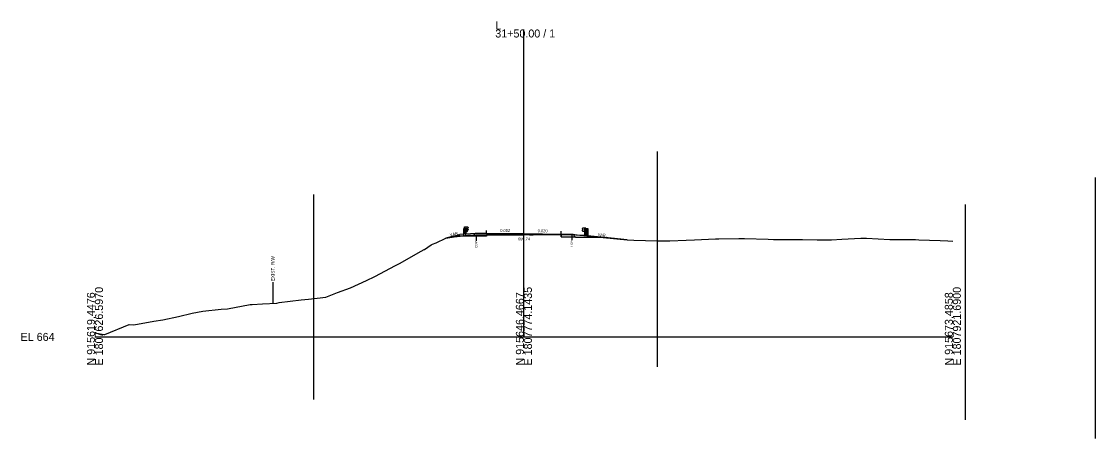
# Model space of a CAD drawing. Extents: x -26 to 1352, y -510 to 9596.
# Drawn here: x 974.3 to 1349.9, y 7464.5 to 7610.3 of the extents above; entities that cross this region are included whole.
import ezdxf

# ---------------------------------------------------------------- set-up
doc = ezdxf.new("R2010")
doc.units = 0
for name, color, linetype in [('Exist Cross Section Cell', 7, 'Continuous'), ('Exist XS Center Line Elevation Label', 7, 'Continuous'), ('Exist XS Ground Line', 7, 'Continuous'), ('Old_Level_10', 7, 'Continuous'), ('Prop XS Ditch Slope Text', 7, 'Continuous'), ('Prop XS Earthwork Shape', 7, 'Continuous'), ('Prop XS EOT Tick Mark', 7, 'Continuous'), ('Prop XS Exc Vertical Line 1', 7, 'Continuous'), ('Prop XS Exc Vertical Line 2', 7, 'Continuous'), ('Prop XS Exc Vertical Line 3', 7, 'Continuous'), ('Prop XS Exc Vertical Line 4', 7, 'Continuous'), ('Prop XS Finish Grade', 7, 'Continuous'), ('Prop XS Finish Grade Earthwork', 7, 'Continuous'), ('Prop XS Finish Grade Paved Shoulder', 7, 'Continuous'), ('Prop XS Finish Grade Pavement', 7, 'Continuous'), ('Prop XS Guardrail', 7, 'Continuous'), ('Prop XS Pvmt Edge Slope', 7, 'Continuous'), ('Prop XS SE Text', 7, 'Continuous'), ('Prop XS Subgrade Earthwork', 7, 'Continuous'), ('Scratch_Level_6', 7, 'Continuous')]:
    doc.layers.add(name, color=color, linetype=linetype)

msp = doc.modelspace()

# ---------------------------------------------------------------- linework, layer by layer
at = {"layer": 'Exist Cross Section Cell'}
for p, q in [((1150, 7500), (1150, 7607.46)), ((1000, 7500), (1150, 7500)), ((1150, 7500), (1300, 7500))]:
    msp.add_line(p, q, dxfattribs=at)
at = {"layer": 'Exist XS Ground Line'}
msp.add_lwpolyline([(1000, 7501.46), (1003.07, 7500.9), (1003.4, 7500.86), (1003.46, 7500.86), (1011.99, 7504.38), (1013.63, 7504.24), (1020.58, 7505.51), (1023.79, 7505.98), (1029.18, 7507.19), (1033.96, 7508.32), (1037.77, 7509.01), (1044.12, 7509.68), (1046.36, 7509.82), (1054.29, 7511.33), (1054.96, 7511.36), (1058.58, 7511.59), (1063.55, 7511.83), (1064.46, 7511.97), (1072.14, 7512.93), (1074.62, 7513.25), (1080.73, 7513.88), (1084.79, 7515.53), (1089.33, 7517.18), (1094.96, 7519.77), (1097.92, 7521.17), (1105.12, 7524.92), (1106.51, 7525.64), (1114.1, 7529.93), (1115.1, 7530.5), (1115.29, 7530.6), (1117.61, 7532.13), (1118.09, 7532.44), (1119.28, 7532.94), (1122.72, 7534.5), (1125.6, 7534.97), (1130.31, 7535.57), (1132.65, 7535.63), (1133.11, 7535.62), (1133.26, 7535.63), (1134.49, 7535.63), (1134.87, 7535.63), (1134.93, 7535.64), (1137, 7535.64), (1137.38, 7535.65), (1137.67, 7535.65), (1139.92, 7535.69), (1140.8, 7535.68), (1142.46, 7535.68), (1143.61, 7535.67), (1145, 7535.68), (1146.65, 7535.71), (1147.71, 7535.72), (1147.9, 7535.72), (1148.95, 7535.72), (1149.15, 7535.72), (1149.26, 7535.72), (1149.89, 7535.73), (1150, 7535.74), (1150.09, 7535.74), (1150.36, 7535.74), (1151.93, 7535.72), (1152.63, 7535.71), (1153.22, 7535.72), (1155.17, 7535.76), (1156.33, 7535.75), (1157.7, 7535.75), (1159.45, 7535.77), (1160.24, 7535.78), (1161.83, 7535.8), (1161.86, 7535.8), (1161.91, 7535.8), (1162.79, 7535.79), (1163.8, 7535.79), (1165.33, 7535.79), (1165.5, 7535.8), (1166.71, 7535.82), (1170.98, 7535.42), (1172, 7535.32), (1172.3, 7535.3), (1172.44, 7535.28), (1173.08, 7535.22), (1174.13, 7535.13), (1186.13, 7533.94), (1188.4, 7533.86), (1196.62, 7533.53), (1201.03, 7533.6), (1206.79, 7533.85), (1209.62, 7533.97), (1216.95, 7534.31), (1218.22, 7534.34), (1225.13, 7534.39), (1226.81, 7534.4), (1227.12, 7534.4), (1235.4, 7534.14), (1237.28, 7534.1), (1244, 7534.05), (1247.45, 7534.01), (1252.59, 7533.92), (1257.62, 7533.98), (1261.18, 7534.14), (1267.78, 7534.56), (1269.77, 7534.54), (1277.95, 7534.04), (1278.37, 7534.02), (1280.65, 7534.01), (1286.96, 7534.03), (1288.12, 7533.91), (1295.55, 7533.66), (1298.28, 7533.59), (1300, 7533.49)], dxfattribs=at)
at = {"layer": 'Old_Level_10'}
for p, q in [((1133.26, 7535.63), (1133.26, 7533.58)), ((1166.71, 7535.82), (1166.71, 7533.77)), ((1062.2, 7519.17), (1062.2, 7511.77))]:
    msp.add_line(p, q, dxfattribs=at)
at = {"layer": 'Prop XS Earthwork Shape'}
for points in [[(1125.6, 7534.97), (1127.74, 7535.25), (1125.39, 7535.24), (1122.72, 7534.5)], [(1122.72, 7534.5), (1125.39, 7535.24), (1127.74, 7535.25), (1125.6, 7534.97)], [(1122.72, 7534.5), (1125.39, 7535.24), (1127.74, 7535.25), (1125.6, 7534.97)], [(1122.72, 7534.5), (1125.39, 7535.24), (1127.74, 7535.25), (1125.6, 7534.97)], [(1125.6, 7534.97), (1127.74, 7535.25), (1125.39, 7535.24), (1122.72, 7534.5)], [(1134.49, 7535.63), (1134.87, 7535.63), (1134.93, 7535.64), (1136.91, 7535.64), (1136.91, 7535.26), (1131.99, 7535.25), (1127.74, 7535.25), (1130.31, 7535.57), (1132.65, 7535.63), (1133.11, 7535.62), (1133.26, 7535.63)], [(1127.74, 7535.25), (1130.31, 7535.57), (1132.65, 7535.63), (1133.11, 7535.62), (1133.26, 7535.63), (1134.49, 7535.63), (1134.87, 7535.63), (1134.93, 7535.64), (1136.91, 7535.64), (1136.91, 7535.26), (1131.99, 7535.25)], [(1133.11, 7535.62), (1133.26, 7535.63), (1134.49, 7535.63), (1134.87, 7535.63), (1134.93, 7535.64), (1136.91, 7535.64), (1136.91, 7535.26), (1131.99, 7535.25), (1127.74, 7535.25), (1130.31, 7535.57), (1132.65, 7535.63)], [(1133.11, 7535.62), (1133.26, 7535.63), (1134.49, 7535.63), (1134.87, 7535.63), (1134.93, 7535.64), (1136.91, 7535.64), (1136.91, 7535.26), (1131.99, 7535.25), (1127.74, 7535.25), (1130.31, 7535.57), (1132.65, 7535.63)], [(1134.49, 7535.63), (1134.87, 7535.63), (1134.93, 7535.64), (1136.91, 7535.64), (1136.91, 7535.26), (1131.99, 7535.25), (1127.74, 7535.25), (1130.31, 7535.57), (1132.65, 7535.63), (1133.11, 7535.62), (1133.26, 7535.63)], [(1173.08, 7535.22), (1174.13, 7535.13), (1178.3, 7534.72), (1168.03, 7534.92), (1163.09, 7535.02), (1163.09, 7535.79), (1163.8, 7535.79), (1165.33, 7535.79), (1165.5, 7535.8), (1166.71, 7535.82), (1170.98, 7535.42), (1172, 7535.32), (1172.3, 7535.3), (1172.44, 7535.28)], [(1174.13, 7535.13), (1178.3, 7534.72), (1168.03, 7534.92), (1163.09, 7535.02), (1163.09, 7535.79), (1163.8, 7535.79), (1165.33, 7535.79), (1165.5, 7535.8), (1166.71, 7535.82), (1170.98, 7535.42), (1172, 7535.32), (1172.3, 7535.3), (1172.44, 7535.28), (1173.08, 7535.22)], [(1163.09, 7535.79), (1163.8, 7535.79), (1165.33, 7535.79), (1165.5, 7535.8), (1166.71, 7535.82), (1170.98, 7535.42), (1172, 7535.32), (1172.3, 7535.3), (1172.44, 7535.28), (1173.08, 7535.22), (1174.13, 7535.13), (1178.3, 7534.72), (1168.03, 7534.92), (1163.09, 7535.02)], [(1163.09, 7535.79), (1163.8, 7535.79), (1165.33, 7535.79), (1165.5, 7535.8), (1166.71, 7535.82), (1170.98, 7535.42), (1172, 7535.32), (1172.3, 7535.3), (1172.44, 7535.28), (1173.08, 7535.22), (1174.13, 7535.13), (1178.3, 7534.72), (1168.03, 7534.92), (1163.09, 7535.02)], [(1173.08, 7535.22), (1174.13, 7535.13), (1178.3, 7534.72), (1168.03, 7534.92), (1163.09, 7535.02), (1163.09, 7535.79), (1163.8, 7535.79), (1165.33, 7535.79), (1165.5, 7535.8), (1166.71, 7535.82), (1170.98, 7535.42), (1172, 7535.32), (1172.3, 7535.3), (1172.44, 7535.28)], [(1179.32, 7534.7), (1186.13, 7533.94), (1178.3, 7534.72)], [(1179.32, 7534.7), (1186.13, 7533.94), (1178.3, 7534.72)], [(1179.32, 7534.7), (1186.13, 7533.94), (1178.3, 7534.72)], [(1179.32, 7534.7), (1186.13, 7533.94), (1178.3, 7534.72)]]:
    msp.add_lwpolyline(points, close=True, dxfattribs=at)
at = {"layer": 'Prop XS EOT Tick Mark'}
for p, q in [((1136.91, 7536.18), (1136.91, 7537.18)), ((1163.09, 7535.94), (1163.09, 7536.94))]:
    msp.add_line(p, q, dxfattribs=at)
at = {"layer": 'Prop XS Exc Vertical Line 1'}
msp.add_line((1076.49, 7478.17), (1076.49, 7549.82), dxfattribs=at)
at = {"layer": 'Prop XS Exc Vertical Line 2'}
msp.add_line((1196.7, 7489.53), (1196.7, 7564.76), dxfattribs=at)
at = {"layer": 'Prop XS Exc Vertical Line 3'}
msp.add_line((1304.41, 7471), (1304.41, 7546.24), dxfattribs=at)
at = {"layer": 'Prop XS Exc Vertical Line 4'}
msp.add_line((1349.89, 7464.49), (1349.89, 7555.68), dxfattribs=at)
at = {"layer": 'Prop XS Finish Grade'}
for p, q in [((1125.39, 7535.24), (1127.56, 7535.84)), ((1128.91, 7535.93), (1127.56, 7535.84)), ((1131.33, 7536.08), (1128.91, 7535.93)), ((1132.91, 7536.17), (1131.33, 7536.08)), ((1167.09, 7535.86), (1168.67, 7535.73)), ((1168.67, 7535.73), (1171.09, 7535.54)), ((1171.09, 7535.54), (1173.36, 7535.36)), ((1173.36, 7535.36), (1179.32, 7534.7))]:
    msp.add_line(p, q, dxfattribs=at)
at = {"layer": 'Prop XS Finish Grade Earthwork'}
for p, q in [((1122.72, 7534.5), (1125.39, 7535.24)), ((1179.32, 7534.7), (1186.13, 7533.94))]:
    msp.add_line(p, q, dxfattribs=at)
at = {"layer": 'Prop XS Finish Grade Paved Shoulder'}
for p, q in [((1136.91, 7536.18), (1132.91, 7536.17)), ((1163.09, 7535.94), (1167.09, 7535.86))]:
    msp.add_line(p, q, dxfattribs=at)
at = {"layer": 'Prop XS Finish Grade Pavement'}
for p, q in [((1136.91, 7536.18), (1150, 7536.2)), ((1150, 7536.2), (1163.09, 7535.94))]:
    msp.add_line(p, q, dxfattribs=at)
at = {"layer": 'Prop XS Guardrail'}
for p, q in [((1129.23, 7538.42), (1129.73, 7538.42)), ((1129.23, 7535.92), (1129.23, 7538.42)), ((1129.73, 7538.42), (1129.73, 7535.92)), ((1129.73, 7538.42), (1130.23, 7538.42)), ((1130.23, 7538.42), (1130.52, 7538.22)), ((1130.52, 7538.1), (1130.23, 7537.9)), ((1130.52, 7538.22), (1130.55, 7538.16)), ((1130.55, 7538.16), (1130.52, 7538.1)), ((1170.66, 7538.04), (1170.37, 7537.84)), ((1171.16, 7538.04), (1170.66, 7538.04)), ((1171.16, 7538.04), (1171.16, 7535.54)), ((1171.66, 7538.04), (1171.16, 7538.04)), ((1171.66, 7535.54), (1171.66, 7538.04)), ((1130.23, 7537.28), (1129.73, 7537.28)), ((1130.23, 7537.9), (1130.23, 7537.8)), ((1130.23, 7537.8), (1130.52, 7537.6)), ((1130.52, 7537.48), (1130.23, 7537.28)), ((1130.52, 7537.6), (1130.55, 7537.54)), ((1130.55, 7537.54), (1130.52, 7537.48)), ((1170.37, 7537.84), (1170.34, 7537.78)), ((1170.34, 7537.78), (1170.37, 7537.72)), ((1170.37, 7537.23), (1170.34, 7537.17)), ((1170.34, 7537.17), (1170.37, 7537.11)), ((1170.37, 7537.72), (1170.66, 7537.52)), ((1170.66, 7537.43), (1170.37, 7537.23)), ((1170.37, 7537.11), (1170.66, 7536.91)), ((1170.66, 7537.52), (1170.66, 7537.43)), ((1170.66, 7536.91), (1171.16, 7536.91))]:
    msp.add_line(p, q, dxfattribs=at)
at = {"layer": 'Prop XS Pvmt Edge Slope'}
for p, q in [((1132.91, 7536.17), (1131.99, 7535.25)), ((1167.09, 7535.86), (1168.03, 7534.92))]:
    msp.add_line(p, q, dxfattribs=at)
at = {"layer": 'Prop XS Subgrade Earthwork'}
for p, q in [((1131.99, 7535.25), (1125.39, 7535.24)), ((1136.91, 7535.26), (1131.99, 7535.25)), ((1136.91, 7535.26), (1136.91, 7535.64)), ((1163.09, 7535.79), (1163.09, 7535.02)), ((1163.09, 7535.02), (1168.03, 7534.92)), ((1168.03, 7534.92), (1179.32, 7534.7))]:
    msp.add_line(p, q, dxfattribs=at)
at = {"layer": 'Scratch_Level_6'}
for p, q in [((1129.02, 7535.38), (1129.02, 7537.88)), ((1129.02, 7537.88), (1129.52, 7537.88)), ((1129.52, 7537.88), (1129.52, 7535.38)), ((1129.52, 7537.88), (1130.02, 7537.88)), ((1130.02, 7536.75), (1129.52, 7536.75)), ((1130.02, 7537.88), (1130.31, 7537.68)), ((1130.31, 7537.56), (1130.02, 7537.36)), ((1130.02, 7537.36), (1130.02, 7537.27)), ((1130.02, 7537.27), (1130.31, 7537.07)), ((1130.31, 7536.95), (1130.02, 7536.75)), ((1130.31, 7537.68), (1130.34, 7537.62)), ((1130.34, 7537.62), (1130.31, 7537.56)), ((1130.31, 7537.07), (1130.34, 7537.01)), ((1130.34, 7537.01), (1130.31, 7536.95)), ((1171.23, 7537.52), (1171.2, 7537.46)), ((1171.2, 7537.46), (1171.23, 7537.4)), ((1171.23, 7536.9), (1171.2, 7536.84)), ((1171.2, 7536.84), (1171.23, 7536.78)), ((1171.52, 7537.72), (1171.23, 7537.52)), ((1171.23, 7537.4), (1171.52, 7537.2)), ((1171.52, 7537.1), (1171.23, 7536.9)), ((1171.23, 7536.78), (1171.52, 7536.58)), ((1172.02, 7537.72), (1171.52, 7537.72)), ((1171.52, 7537.2), (1171.52, 7537.1)), ((1171.52, 7536.58), (1172.02, 7536.58)), ((1172.52, 7537.72), (1172.02, 7537.72)), ((1172.02, 7537.72), (1172.02, 7535.22)), ((1172.52, 7535.22), (1172.52, 7537.72))]:
    msp.add_line(p, q, dxfattribs=at)

# ---------------------------------------------------------------- texts
at = {"layer": 'Exist Cross Section Cell'}
for s, p in [('L', (1140, 7607.46)), ('31+50.00 / 1', (1140, 7604.66)), ('EL 664', (974, 7498.6))]:
    msp.add_text(s, height=2.8, dxfattribs=at).set_placement(p)
for s, p in [('E 1807626.5970', (1002.8, 7490)), ('E 1807774.1435', (1152.8, 7490)), ('E 1807921.6900', (1302.8, 7490)), ('N 915619.4476', (1000, 7490)), ('N 915646.4667', (1150, 7490)), ('N 915673.4858', (1300, 7490))]:
    msp.add_text(s, height=2.8, rotation=90, dxfattribs=at).set_placement(p)
at = {"layer": 'Exist XS Center Line Elevation Label'}
msp.add_text('699.74', height=1, dxfattribs=at).set_placement((1147.95, 7533.74))
at = {"layer": 'Old_Level_10'}
for s, height, p in [('EOP', 0.787, (1133.66, 7531.18)), ('EOP', 0.787, (1167.1, 7531.37)), ('EXIST. R/W', 1.181, (1062.79, 7519.47))]:
    msp.add_text(s, height=height, rotation=90, dxfattribs=at).set_placement(p)
at = {"layer": 'Prop XS Ditch Slope Text'}
for rotation, p in [(14.0362, (1124.23, 7535.13)), (353.6343, (1175.73, 7535.3))]:
    msp.add_text('VAR.', height=1, rotation=rotation, dxfattribs=at).set_placement(p)
at = {"layer": 'Prop XS SE Text'}
for s, rotation, p in [('0.002', 0.0996, (1141.74, 7536.69)), ('0.020', 358.8542, (1154.8, 7536.61))]:
    msp.add_text(s, height=1, rotation=rotation, dxfattribs=at).set_placement(p)

doc.saveas('drawing.dxf')
